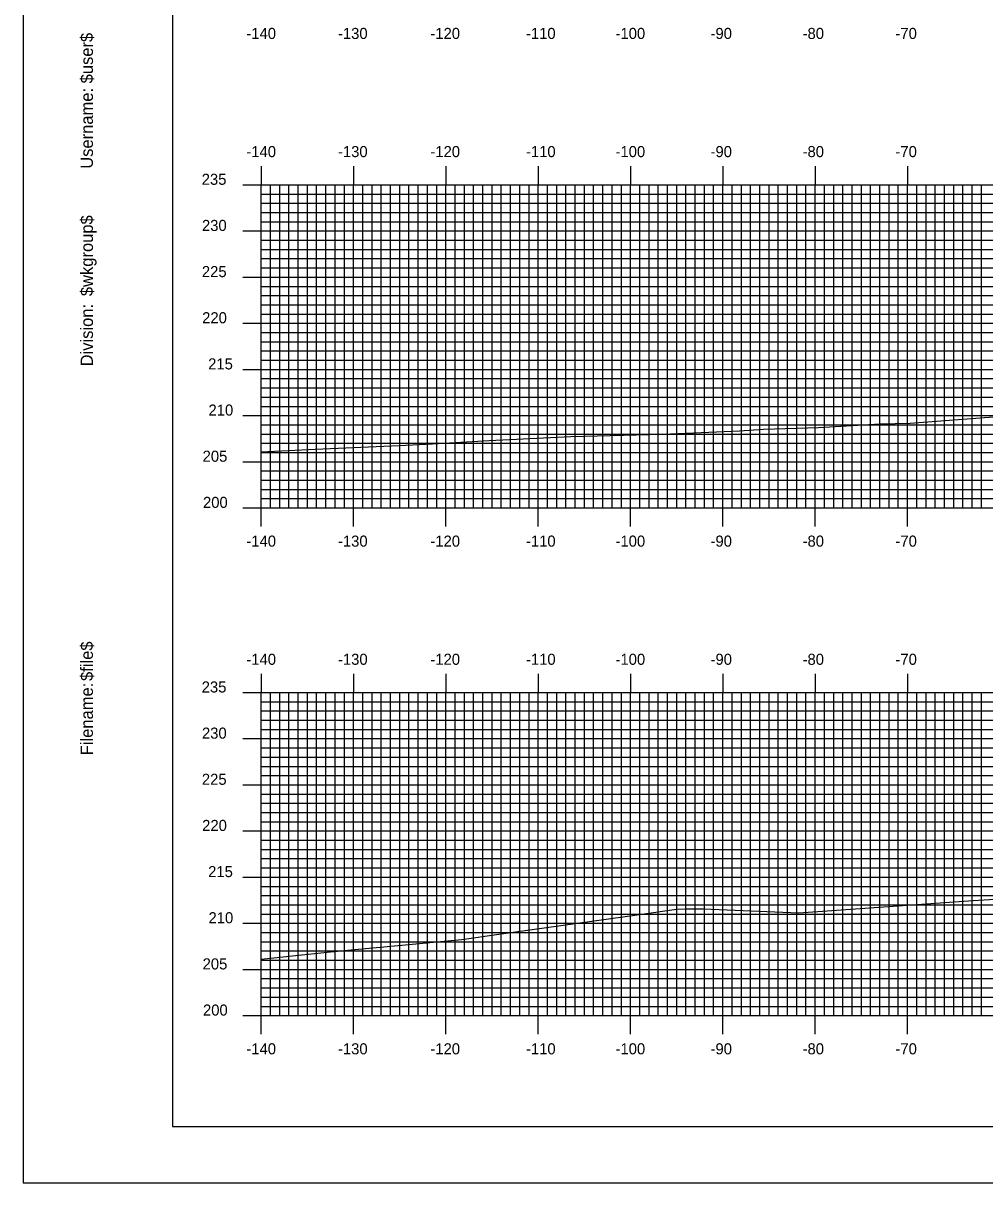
# Model space of a CAD drawing. Extents: x 851742 to 852085, y 364785 to 365005.
# Drawn here: x 851741.9 to 851846.1, y 364785.1 to 364910.7 of the extents above; entities that cross this region are included whole.
import ezdxf

# ---------------------------------------------------------------- set-up
doc = ezdxf.new("R2010")
doc.units = 0
for name, color, linetype in [('BORDER', 7, 'Continuous'), ('H_V ANNOTATION', 7, 'Continuous'), ('MAJOR', 7, 'Continuous'), ('MINOR', 7, 'Continuous'), ('PLOT BOUNDARY', 7, 'Continuous'), ('S_Roadway_Centerline', 7, 'Continuous')]:
    doc.layers.add(name, color=color, linetype=linetype)

msp = doc.modelspace()

# ---------------------------------------------------------------- linework, layer by layer
at = {"layer": 'BORDER'}
msp.add_lwpolyline([(851758.1, 364791.23), (852078.1, 364791.23), (852078.1, 365001.23), (851758.1, 365001.23)], close=True, dxfattribs=at)
at = {"layer": 'MAJOR'}
for p, q in [((851767.7, 364895.24), (851767.7, 364893.23)), ((851777.7, 364895.24), (851777.7, 364893.23)), ((851787.7, 364895.24), (851787.7, 364893.23)), ((851797.7, 364895.24), (851797.7, 364893.23)), ((851807.7, 364895.24), (851807.7, 364893.23)), ((851817.7, 364895.24), (851817.7, 364893.23)), ((851827.7, 364895.24), (851827.7, 364893.23)), ((851837.7, 364895.24), (851837.7, 364893.23)), ((851765.7, 364893.23), (851767.7, 364893.23)), ((851767.7, 364893.23), (852047.7, 364893.23)), ((851767.7, 364858.23), (851767.7, 364893.23)), ((851767.7, 364858.23), (851767.7, 364893.23)), ((851767.7, 364893.23), (852047.7, 364893.23)), ((851777.7, 364858.23), (851777.7, 364893.23)), ((851787.7, 364858.23), (851787.7, 364893.23)), ((851797.7, 364858.23), (851797.7, 364893.23)), ((851807.7, 364858.23), (851807.7, 364893.23)), ((851817.7, 364858.23), (851817.7, 364893.23)), ((851827.7, 364858.23), (851827.7, 364893.23)), ((851837.7, 364858.23), (851837.7, 364893.23)), ((851765.7, 364888.23), (851767.7, 364888.23)), ((851767.7, 364888.23), (852047.7, 364888.23)), ((851765.7, 364883.23), (851767.7, 364883.23)), ((851767.7, 364883.23), (852047.7, 364883.23)), ((851765.7, 364878.23), (851767.7, 364878.23)), ((851767.7, 364878.23), (852047.7, 364878.23)), ((851765.7, 364873.23), (851767.7, 364873.23)), ((851767.7, 364873.23), (852047.7, 364873.23)), ((851765.7, 364868.23), (851767.7, 364868.23)), ((851767.7, 364868.23), (852047.7, 364868.23)), ((851765.7, 364863.23), (851767.7, 364863.23)), ((851767.7, 364863.23), (852047.7, 364863.23)), ((851765.7, 364858.23), (851767.7, 364858.23)), ((851767.7, 364858.23), (852047.7, 364858.23)), ((851767.7, 364858.23), (852047.7, 364858.23)), ((851767.7, 364856.23), (851767.7, 364858.23)), ((851777.7, 364856.23), (851777.7, 364858.23)), ((851787.7, 364856.23), (851787.7, 364858.23)), ((851797.7, 364856.23), (851797.7, 364858.23)), ((851807.7, 364856.23), (851807.7, 364858.23)), ((851817.7, 364856.23), (851817.7, 364858.23)), ((851827.7, 364856.23), (851827.7, 364858.23)), ((851837.7, 364856.23), (851837.7, 364858.23)), ((851767.7, 364840.24), (851767.7, 364838.23)), ((851777.7, 364840.24), (851777.7, 364838.23)), ((851787.7, 364840.24), (851787.7, 364838.23)), ((851797.7, 364840.24), (851797.7, 364838.23)), ((851807.7, 364840.24), (851807.7, 364838.23)), ((851817.7, 364840.24), (851817.7, 364838.23)), ((851827.7, 364840.24), (851827.7, 364838.23)), ((851837.7, 364840.24), (851837.7, 364838.23)), ((851765.7, 364838.23), (851767.7, 364838.23)), ((851767.7, 364838.23), (852047.7, 364838.23)), ((851767.7, 364803.23), (851767.7, 364838.23)), ((851767.7, 364803.23), (851767.7, 364838.23)), ((851767.7, 364838.23), (852047.7, 364838.23)), ((851777.7, 364803.23), (851777.7, 364838.23)), ((851787.7, 364803.23), (851787.7, 364838.23)), ((851797.7, 364803.23), (851797.7, 364838.23)), ((851807.7, 364803.23), (851807.7, 364838.23)), ((851817.7, 364803.23), (851817.7, 364838.23)), ((851827.7, 364803.23), (851827.7, 364838.23)), ((851837.7, 364803.23), (851837.7, 364838.23)), ((851765.7, 364833.23), (851767.7, 364833.23)), ((851767.7, 364833.23), (852047.7, 364833.23)), ((851765.7, 364828.23), (851767.7, 364828.23)), ((851767.7, 364828.23), (852047.7, 364828.23)), ((851765.7, 364823.23), (851767.7, 364823.23)), ((851767.7, 364823.23), (852047.7, 364823.23)), ((851765.7, 364818.23), (851767.7, 364818.23)), ((851767.7, 364818.23), (852047.7, 364818.23)), ((851765.7, 364813.23), (851767.7, 364813.23)), ((851767.7, 364813.23), (852047.7, 364813.23)), ((851765.7, 364808.23), (851767.7, 364808.23)), ((851767.7, 364808.23), (852047.7, 364808.23)), ((851765.7, 364803.23), (851767.7, 364803.23)), ((851767.7, 364803.23), (852047.7, 364803.23)), ((851767.7, 364803.23), (852047.7, 364803.23)), ((851767.7, 364801.23), (851767.7, 364803.23)), ((851777.7, 364801.23), (851777.7, 364803.23)), ((851787.7, 364801.23), (851787.7, 364803.23)), ((851797.7, 364801.23), (851797.7, 364803.23)), ((851807.7, 364801.23), (851807.7, 364803.23)), ((851817.7, 364801.23), (851817.7, 364803.23)), ((851827.7, 364801.23), (851827.7, 364803.23)), ((851837.7, 364801.23), (851837.7, 364803.23))]:
    msp.add_line(p, q, dxfattribs=at)
at = {"layer": 'MINOR'}
for p, q in [((851768.7, 364858.23), (851768.7, 364893.23)), ((851769.7, 364858.23), (851769.7, 364893.23)), ((851770.7, 364858.23), (851770.7, 364893.23)), ((851771.7, 364858.23), (851771.7, 364893.23)), ((851772.7, 364858.23), (851772.7, 364893.23)), ((851773.7, 364858.23), (851773.7, 364893.23)), ((851774.7, 364858.23), (851774.7, 364893.23)), ((851775.7, 364858.23), (851775.7, 364893.23)), ((851776.7, 364858.23), (851776.7, 364893.23)), ((851778.7, 364858.23), (851778.7, 364893.23)), ((851779.7, 364858.23), (851779.7, 364893.23)), ((851780.7, 364858.23), (851780.7, 364893.23)), ((851781.7, 364858.23), (851781.7, 364893.23)), ((851782.7, 364858.23), (851782.7, 364893.23)), ((851783.7, 364858.23), (851783.7, 364893.23)), ((851784.7, 364858.23), (851784.7, 364893.23)), ((851785.7, 364858.23), (851785.7, 364893.23)), ((851786.7, 364858.23), (851786.7, 364893.23)), ((851788.7, 364858.23), (851788.7, 364893.23)), ((851789.7, 364858.23), (851789.7, 364893.23)), ((851790.7, 364858.23), (851790.7, 364893.23)), ((851791.7, 364858.23), (851791.7, 364893.23)), ((851792.7, 364858.23), (851792.7, 364893.23)), ((851793.7, 364858.23), (851793.7, 364893.23)), ((851794.7, 364858.23), (851794.7, 364893.23)), ((851795.7, 364858.23), (851795.7, 364893.23)), ((851796.7, 364858.23), (851796.7, 364893.23)), ((851798.7, 364858.23), (851798.7, 364893.23)), ((851799.7, 364858.23), (851799.7, 364893.23)), ((851800.7, 364858.23), (851800.7, 364893.23)), ((851801.7, 364858.23), (851801.7, 364893.23)), ((851802.7, 364858.23), (851802.7, 364893.23)), ((851803.7, 364858.23), (851803.7, 364893.23)), ((851804.7, 364858.23), (851804.7, 364893.23)), ((851805.7, 364858.23), (851805.7, 364893.23)), ((851806.7, 364858.23), (851806.7, 364893.23)), ((851808.7, 364858.23), (851808.7, 364893.23)), ((851809.7, 364858.23), (851809.7, 364893.23)), ((851810.7, 364858.23), (851810.7, 364893.23)), ((851811.7, 364858.23), (851811.7, 364893.23)), ((851812.7, 364858.23), (851812.7, 364893.23)), ((851813.7, 364858.23), (851813.7, 364893.23)), ((851814.7, 364858.23), (851814.7, 364893.23)), ((851815.7, 364858.23), (851815.7, 364893.23)), ((851816.7, 364858.23), (851816.7, 364893.23)), ((851818.7, 364858.23), (851818.7, 364893.23)), ((851819.7, 364858.23), (851819.7, 364893.23)), ((851820.7, 364858.23), (851820.7, 364893.23)), ((851821.7, 364858.23), (851821.7, 364893.23)), ((851822.7, 364858.23), (851822.7, 364893.23)), ((851823.7, 364858.23), (851823.7, 364893.23)), ((851824.7, 364858.23), (851824.7, 364893.23)), ((851825.7, 364858.23), (851825.7, 364893.23)), ((851826.7, 364858.23), (851826.7, 364893.23)), ((851828.7, 364858.23), (851828.7, 364893.23)), ((851829.7, 364858.23), (851829.7, 364893.23)), ((851830.7, 364858.23), (851830.7, 364893.23)), ((851831.7, 364858.23), (851831.7, 364893.23)), ((851832.7, 364858.23), (851832.7, 364893.23)), ((851833.7, 364858.23), (851833.7, 364893.23)), ((851834.7, 364858.23), (851834.7, 364893.23)), ((851835.7, 364858.23), (851835.7, 364893.23)), ((851836.7, 364858.23), (851836.7, 364893.23)), ((851838.7, 364858.23), (851838.7, 364893.23)), ((851839.7, 364858.23), (851839.7, 364893.23)), ((851840.7, 364858.23), (851840.7, 364893.23)), ((851841.7, 364858.23), (851841.7, 364893.23)), ((851842.7, 364858.23), (851842.7, 364893.23)), ((851843.7, 364858.23), (851843.7, 364893.23)), ((851844.7, 364858.23), (851844.7, 364893.23)), ((851845.7, 364858.23), (851845.7, 364893.23)), ((851767.7, 364892.23), (852047.7, 364892.23)), ((851767.7, 364892.23), (851769.71, 364892.23)), ((851767.7, 364891.23), (852047.7, 364891.23)), ((851767.7, 364891.23), (851769.71, 364891.23)), ((851767.7, 364890.23), (852047.7, 364890.23)), ((851767.7, 364890.23), (851769.71, 364890.23)), ((851767.7, 364889.23), (852047.7, 364889.23)), ((851767.7, 364889.23), (851769.71, 364889.23)), ((851767.7, 364887.23), (852047.7, 364887.23)), ((851767.7, 364887.23), (851769.71, 364887.23)), ((851767.7, 364886.23), (852047.7, 364886.23)), ((851767.7, 364886.23), (851769.71, 364886.23)), ((851767.7, 364885.23), (852047.7, 364885.23)), ((851767.7, 364885.23), (851769.71, 364885.23)), ((851767.7, 364884.23), (852047.7, 364884.23)), ((851767.7, 364884.23), (851769.71, 364884.23)), ((851767.7, 364882.23), (852047.7, 364882.23)), ((851767.7, 364882.23), (851769.71, 364882.23)), ((851767.7, 364881.23), (852047.7, 364881.23)), ((851767.7, 364881.23), (851769.71, 364881.23)), ((851767.7, 364880.23), (852047.7, 364880.23)), ((851767.7, 364880.23), (851769.71, 364880.23)), ((851767.7, 364879.23), (852047.7, 364879.23)), ((851767.7, 364879.23), (851769.71, 364879.23)), ((851767.7, 364877.23), (852047.7, 364877.23)), ((851767.7, 364877.23), (851769.71, 364877.23)), ((851767.7, 364876.23), (852047.7, 364876.23)), ((851767.7, 364876.23), (851769.71, 364876.23)), ((851767.7, 364875.23), (852047.7, 364875.23)), ((851767.7, 364875.23), (851769.71, 364875.23)), ((851767.7, 364874.23), (852047.7, 364874.23)), ((851767.7, 364874.23), (851769.71, 364874.23)), ((851767.7, 364872.23), (852047.7, 364872.23)), ((851767.7, 364872.23), (851769.71, 364872.23)), ((851767.7, 364871.23), (852047.7, 364871.23)), ((851767.7, 364871.23), (851769.71, 364871.23)), ((851767.7, 364870.23), (852047.7, 364870.23)), ((851767.7, 364870.23), (851769.71, 364870.23)), ((851767.7, 364869.23), (852047.7, 364869.23)), ((851767.7, 364869.23), (851769.71, 364869.23)), ((851767.7, 364867.23), (852047.7, 364867.23)), ((851767.7, 364867.23), (851769.71, 364867.23)), ((851767.7, 364866.23), (852047.7, 364866.23)), ((851767.7, 364866.23), (851769.71, 364866.23)), ((851767.7, 364865.23), (852047.7, 364865.23)), ((851767.7, 364865.23), (851769.71, 364865.23)), ((851767.7, 364864.23), (852047.7, 364864.23)), ((851767.7, 364864.23), (851769.71, 364864.23)), ((851767.7, 364862.23), (852047.7, 364862.23)), ((851767.7, 364862.23), (851769.71, 364862.23)), ((851767.7, 364861.23), (852047.7, 364861.23)), ((851767.7, 364861.23), (851769.71, 364861.23)), ((851767.7, 364860.23), (852047.7, 364860.23)), ((851767.7, 364860.23), (851769.71, 364860.23)), ((851767.7, 364859.23), (852047.7, 364859.23)), ((851767.7, 364859.23), (851769.71, 364859.23)), ((851767.7, 364837.23), (852047.7, 364837.23)), ((851767.7, 364837.23), (851769.71, 364837.23)), ((851768.7, 364803.23), (851768.7, 364838.23)), ((851769.7, 364803.23), (851769.7, 364838.23)), ((851770.7, 364803.23), (851770.7, 364838.23)), ((851771.7, 364803.23), (851771.7, 364838.23)), ((851772.7, 364803.23), (851772.7, 364838.23)), ((851773.7, 364803.23), (851773.7, 364838.23)), ((851774.7, 364803.23), (851774.7, 364838.23)), ((851775.7, 364803.23), (851775.7, 364838.23)), ((851776.7, 364803.23), (851776.7, 364838.23)), ((851778.7, 364803.23), (851778.7, 364838.23)), ((851779.7, 364803.23), (851779.7, 364838.23)), ((851780.7, 364803.23), (851780.7, 364838.23)), ((851781.7, 364803.23), (851781.7, 364838.23)), ((851782.7, 364803.23), (851782.7, 364838.23)), ((851783.7, 364803.23), (851783.7, 364838.23)), ((851784.7, 364803.23), (851784.7, 364838.23)), ((851785.7, 364803.23), (851785.7, 364838.23)), ((851786.7, 364803.23), (851786.7, 364838.23)), ((851788.7, 364803.23), (851788.7, 364838.23)), ((851789.7, 364803.23), (851789.7, 364838.23)), ((851790.7, 364803.23), (851790.7, 364838.23)), ((851791.7, 364803.23), (851791.7, 364838.23)), ((851792.7, 364803.23), (851792.7, 364838.23)), ((851793.7, 364803.23), (851793.7, 364838.23)), ((851794.7, 364803.23), (851794.7, 364838.23)), ((851795.7, 364803.23), (851795.7, 364838.23)), ((851796.7, 364803.23), (851796.7, 364838.23)), ((851798.7, 364803.23), (851798.7, 364838.23)), ((851799.7, 364803.23), (851799.7, 364838.23)), ((851800.7, 364803.23), (851800.7, 364838.23)), ((851801.7, 364803.23), (851801.7, 364838.23)), ((851802.7, 364803.23), (851802.7, 364838.23)), ((851803.7, 364803.23), (851803.7, 364838.23)), ((851804.7, 364803.23), (851804.7, 364838.23)), ((851805.7, 364803.23), (851805.7, 364838.23)), ((851806.7, 364803.23), (851806.7, 364838.23)), ((851808.7, 364803.23), (851808.7, 364838.23)), ((851809.7, 364803.23), (851809.7, 364838.23)), ((851810.7, 364803.23), (851810.7, 364838.23)), ((851811.7, 364803.23), (851811.7, 364838.23)), ((851812.7, 364803.23), (851812.7, 364838.23)), ((851813.7, 364803.23), (851813.7, 364838.23)), ((851814.7, 364803.23), (851814.7, 364838.23)), ((851815.7, 364803.23), (851815.7, 364838.23)), ((851816.7, 364803.23), (851816.7, 364838.23)), ((851818.7, 364803.23), (851818.7, 364838.23)), ((851819.7, 364803.23), (851819.7, 364838.23)), ((851820.7, 364803.23), (851820.7, 364838.23)), ((851821.7, 364803.23), (851821.7, 364838.23)), ((851822.7, 364803.23), (851822.7, 364838.23)), ((851823.7, 364803.23), (851823.7, 364838.23)), ((851824.7, 364803.23), (851824.7, 364838.23)), ((851825.7, 364803.23), (851825.7, 364838.23)), ((851826.7, 364803.23), (851826.7, 364838.23)), ((851828.7, 364803.23), (851828.7, 364838.23)), ((851829.7, 364803.23), (851829.7, 364838.23)), ((851830.7, 364803.23), (851830.7, 364838.23)), ((851831.7, 364803.23), (851831.7, 364838.23)), ((851832.7, 364803.23), (851832.7, 364838.23)), ((851833.7, 364803.23), (851833.7, 364838.23)), ((851834.7, 364803.23), (851834.7, 364838.23)), ((851835.7, 364803.23), (851835.7, 364838.23)), ((851836.7, 364803.23), (851836.7, 364838.23)), ((851838.7, 364803.23), (851838.7, 364838.23)), ((851839.7, 364803.23), (851839.7, 364838.23)), ((851840.7, 364803.23), (851840.7, 364838.23)), ((851841.7, 364803.23), (851841.7, 364838.23)), ((851842.7, 364803.23), (851842.7, 364838.23)), ((851843.7, 364803.23), (851843.7, 364838.23)), ((851844.7, 364803.23), (851844.7, 364838.23)), ((851845.7, 364803.23), (851845.7, 364838.23)), ((851767.7, 364836.23), (852047.7, 364836.23)), ((851767.7, 364836.23), (851769.71, 364836.23)), ((851767.7, 364835.23), (852047.7, 364835.23)), ((851767.7, 364835.23), (851769.71, 364835.23)), ((851767.7, 364834.23), (852047.7, 364834.23)), ((851767.7, 364834.23), (851769.71, 364834.23)), ((851767.7, 364832.23), (852047.7, 364832.23)), ((851767.7, 364832.23), (851769.71, 364832.23)), ((851767.7, 364831.23), (852047.7, 364831.23)), ((851767.7, 364831.23), (851769.71, 364831.23)), ((851767.7, 364830.23), (852047.7, 364830.23)), ((851767.7, 364830.23), (851769.71, 364830.23)), ((851767.7, 364829.23), (852047.7, 364829.23)), ((851767.7, 364829.23), (851769.71, 364829.23)), ((851767.7, 364827.23), (852047.7, 364827.23)), ((851767.7, 364827.23), (851769.71, 364827.23)), ((851767.7, 364826.23), (852047.7, 364826.23)), ((851767.7, 364826.23), (851769.71, 364826.23)), ((851767.7, 364825.23), (852047.7, 364825.23)), ((851767.7, 364825.23), (851769.71, 364825.23)), ((851767.7, 364824.23), (852047.7, 364824.23)), ((851767.7, 364824.23), (851769.71, 364824.23)), ((851767.7, 364822.23), (852047.7, 364822.23)), ((851767.7, 364822.23), (851769.71, 364822.23)), ((851767.7, 364821.23), (852047.7, 364821.23)), ((851767.7, 364821.23), (851769.71, 364821.23)), ((851767.7, 364820.23), (852047.7, 364820.23)), ((851767.7, 364820.23), (851769.71, 364820.23)), ((851767.7, 364819.23), (852047.7, 364819.23)), ((851767.7, 364819.23), (851769.71, 364819.23)), ((851767.7, 364817.23), (852047.7, 364817.23)), ((851767.7, 364817.23), (851769.71, 364817.23)), ((851767.7, 364816.23), (852047.7, 364816.23)), ((851767.7, 364816.23), (851769.71, 364816.23)), ((851767.7, 364815.23), (852047.7, 364815.23)), ((851767.7, 364815.23), (851769.71, 364815.23)), ((851767.7, 364814.23), (852047.7, 364814.23)), ((851767.7, 364814.23), (851769.71, 364814.23)), ((851767.7, 364812.23), (852047.7, 364812.23)), ((851767.7, 364812.23), (851769.71, 364812.23)), ((851767.7, 364811.23), (852047.7, 364811.23)), ((851767.7, 364811.23), (851769.71, 364811.23)), ((851767.7, 364810.23), (852047.7, 364810.23)), ((851767.7, 364810.23), (851769.71, 364810.23)), ((851767.7, 364809.23), (852047.7, 364809.23)), ((851767.7, 364809.23), (851769.71, 364809.23)), ((851767.7, 364807.23), (852047.7, 364807.23)), ((851767.7, 364807.23), (851769.71, 364807.23)), ((851767.7, 364806.23), (852047.7, 364806.23)), ((851767.7, 364806.23), (851769.71, 364806.23)), ((851767.7, 364805.23), (852047.7, 364805.23)), ((851767.7, 364805.23), (851769.71, 364805.23)), ((851767.7, 364804.23), (852047.7, 364804.23)), ((851767.7, 364804.23), (851769.71, 364804.23))]:
    msp.add_line(p, q, dxfattribs=at)
at = {"layer": 'PLOT BOUNDARY'}
msp.add_lwpolyline([(851741.92, 364785.11), (852081.92, 364785.11), (852081.92, 365005.11), (851741.92, 365005.11)], close=True, dxfattribs=at)
at = {"layer": 'S_Roadway_Centerline'}
for points in [[(851767.7, 364864.3), (851773.54, 364864.6), (851782.62, 364864.99), (851786.25, 364865.18), (851792.38, 364865.52), (851801.22, 364865.98), (851811.18, 364866.22), (851819.51, 364866.58), (851822.09, 364866.75), (851828.05, 364866.94), (851834.75, 364867.33), (851837.99, 364867.41), (851847.95, 364868.16)], [(851767.7, 364809.36), (851772.09, 364809.82), (851774.83, 364810.11), (851777.44, 364810.36), (851782.53, 364810.83), (851789.42, 364811.46), (851793.44, 364812.05), (851808.67, 364814.19), (851812.68, 364814.76), (851813.61, 364814.78), (851815.55, 364814.81), (851825.92, 364814.35), (851844.81, 364815.69), (851850.68, 364816.07)]]:
    msp.add_lwpolyline(points, dxfattribs=at)

# ---------------------------------------------------------------- texts
at = {"layer": 'BORDER'}
for s, p in [('$user$', (851749.47, 364904.22)), ('Username:', (851749.47, 364894.97)), ('$wkgroup$', (851749.47, 364881.17)), ('Division:', (851749.47, 364873.56)), ('$file$', (851749.47, 364839.48)), ('Filename:', (851749.47, 364831.43))]:
    msp.add_text(s, height=1.339, rotation=90, dxfattribs=at).set_placement(p)
at = {"layer": 'H_V ANNOTATION'}
for s, p in [('-140', (851766.09, 364909.03)), ('-130', (851776.01, 364909.03)), ('-120', (851786.02, 364909.03)), ('-110', (851796.37, 364909.03)), ('-100', (851806.07, 364909.03)), ('-90', (851816.36, 364909.03)), ('-80', (851826.33, 364909.03)), ('-70', (851836.39, 364909.03)), ('-140', (851766.09, 364896.23)), ('-130', (851776.01, 364896.23)), ('-120', (851786.02, 364896.23)), ('-110', (851796.37, 364896.23)), ('-100', (851806.07, 364896.23)), ('-90', (851816.36, 364896.23)), ('-80', (851826.33, 364896.23)), ('-70', (851836.39, 364896.23)), ('235', (851761.25, 364893.23)), ('230', (851761.28, 364888.23)), ('225', (851761.27, 364883.23)), ('220', (851761.3, 364878.23)), ('215', (851761.95, 364873.23)), ('210', (851761.99, 364868.23)), ('205', (851761.35, 364863.23)), ('200', (851761.39, 364858.23)), ('-140', (851766.09, 364854.03)), ('-130', (851776.01, 364854.03)), ('-120', (851786.02, 364854.03)), ('-110', (851796.37, 364854.03)), ('-100', (851806.07, 364854.03)), ('-90', (851816.36, 364854.03)), ('-80', (851826.33, 364854.03)), ('-70', (851836.39, 364854.03)), ('-140', (851766.09, 364841.23)), ('-130', (851776.01, 364841.23)), ('-120', (851786.02, 364841.23)), ('-110', (851796.37, 364841.23)), ('-100', (851806.07, 364841.23)), ('-90', (851816.36, 364841.23)), ('-80', (851826.33, 364841.23)), ('-70', (851836.39, 364841.23)), ('235', (851761.25, 364838.23)), ('230', (851761.28, 364833.23)), ('225', (851761.27, 364828.23)), ('220', (851761.3, 364823.23)), ('215', (851761.95, 364818.23)), ('210', (851761.99, 364813.23)), ('205', (851761.35, 364808.23)), ('200', (851761.39, 364803.23)), ('-140', (851766.09, 364799.03)), ('-130', (851776.01, 364799.03)), ('-120', (851786.02, 364799.03)), ('-110', (851796.37, 364799.03)), ('-100', (851806.07, 364799.03)), ('-90', (851816.36, 364799.03)), ('-80', (851826.33, 364799.03)), ('-70', (851836.39, 364799.03))]:
    msp.add_text(s, height=1.2, dxfattribs=at).set_placement(p)
at = {"layer": 'MAJOR'}
for p in [(851767.7, 364858.23), (851767.7, 364803.23)]:
    msp.add_text('-', height=0.012, dxfattribs=at).set_placement(p)

doc.saveas('drawing.dxf')
